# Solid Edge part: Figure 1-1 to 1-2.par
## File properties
Author: CADCIM
Template: normal.par
Last saved by: CADCIM
Revision: 14
Application: Solid Edge
Accuracy: 0.99
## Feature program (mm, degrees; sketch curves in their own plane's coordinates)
sketch for "unnamed Protrusion 1" plane through (0, 0, 0) normal (0, 0, 1) x-axis (1, 0, 0)
  line (-63.0032, 49) -> (-56, -71)
  line (-56, -71) -> (56, -71)
  line (56, -71) -> (63.0032, 49)
  line (63.0032, 49) -> (0, 54)
  line (0, 54) -> (-63.0032, 49)
  dimension (linear) = 56
  dimension (linear) = 56
extrude "unnamed Protrusion 1" add finite 4 along +normal
fillet "Round_1" radius 15
sketch for "ExtrudedProtrusion_3" plane through (0, -8.5, 0) normal (0, 0, -1) x-axis (-1, 0, 0)
extrude "ExtrudedProtrusion_3" add finite 12 along -normal
pattern "unnamed Pattern 1" of "ExtrudedProtrusion_3"
pattern "unnamed Pattern 2"
sketch for "unnamed Protrusion 2" plane through (-1.0316, 2.3101, 4) normal (0, 0, 1) x-axis (-1, 0, 0)
extrude "unnamed Protrusion 2" add finite 5 along +normal
sketch for "Hole_22" plane through (40.9331, -54.9887, 12) normal (0, 0, 1) x-axis (1, 0, 0)
  hole centre (-0.4331, -0.0113) bore radius 4.5
hole "Hole_22" diameter 9 through  CounterBoreDepth = 5 mm
pattern "unnamed Pattern 3" of "Hole_22"
hole "unnamed Hole 1" through
hole "unnamed Hole 2" through
hole "unnamed Hole 3" through
sketch for "Hole_29" plane through (-1.0316, -6.1899, 9) normal (0, 0, 1) x-axis (1, 0, 0)
  hole centre (0, 0) bore radius 11
hole "Hole_29" diameter 22 through
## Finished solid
Body 1: solid body, 34 faces, 55 edges, 18 vertices.
  Faces by surface: cylinder 18, plane 16
  Edges by curve: circle 36, line 19
Bounding box of the edges (mm): 124.346 x 125.000 x 12.000, from (-62.1729, -71, 0) to (62.1729, 54, 12).
Cylindrical faces by radius (mm): R4.5 x4, R7.5 x4, R10.7006 x4, R11 x1, R15 x4, R20 x1
Planar faces by outward normal: +z 10, -y 1, -z 1, oblique 4
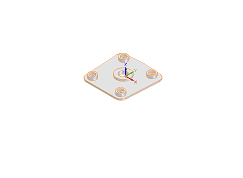
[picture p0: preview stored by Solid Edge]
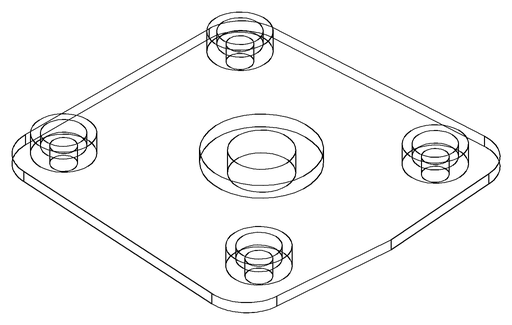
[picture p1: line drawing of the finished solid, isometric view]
